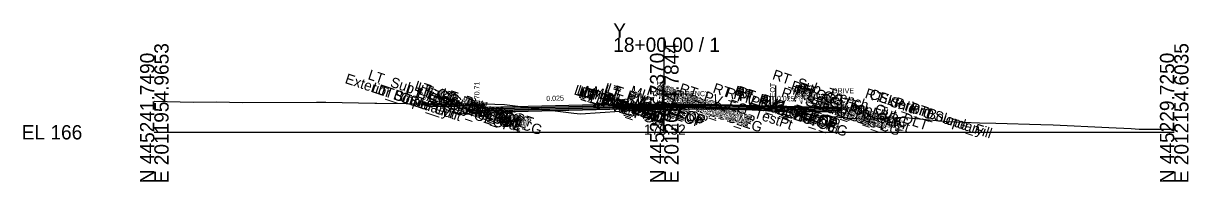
# Model space of a CAD drawing. Extents: x -26 to 3203, y -10 to 9532.
# Drawn here: x 974.3 to 1202.8, y 1990.3 to 2021.4 of the extents above; entities that cross this region are included whole.
import ezdxf

# ---------------------------------------------------------------- set-up
doc = ezdxf.new("R2010")
doc.units = 0
for name, color, linetype in [('Default', 7, 'Continuous'), ('Exist Cross Section Cell', 7, 'Continuous'), ('Exist XS Center Line Elevation Label', 7, 'Continuous'), ('Exist XS Ground Line', 7, 'Continuous'), ('Prop CMT Conc Surface', 7, 'Continuous'), ('Prop CMT Concrete Structures', 7, 'Continuous'), ('Prop CMT Pvmt Course 1', 7, 'Continuous'), ('Prop CMT Pvmt Course 1 CG', 7, 'Continuous'), ('Prop CMT Pvmt Course 1 Wedge', 7, 'Continuous'), ('Prop CMT Pvmt Course 2', 7, 'Continuous'), ('Prop CMT Pvmt Course 2 Wedge', 7, 'Continuous'), ('Prop CMT Pvmt Course 3', 7, 'Continuous'), ('Prop CMT Pvmt Course 3 Wedge', 7, 'Continuous'), ('Prop CMT Pvmt Surface', 7, 'Continuous'), ('Prop CMT Pvmt Wedge Surface 1', 7, 'Continuous'), ('Prop CMT Pvmt Wedge Surface 2', 7, 'Continuous'), ('Prop CMT Pvmt Wedge Surface 3', 7, 'Continuous'), ('Prop CMT Shear Line', 7, 'Continuous'), ('Prop CMT Shear Line Text', 7, 'Continuous'), ('Prop CMT Slope Grass', 7, 'Continuous'), ('Prop CMT Subgrade Earthwork', 7, 'Continuous'), ('Prop XS Hydro Elevations', 7, 'Continuous'), ('Prop XS Label Text', 7, 'Continuous'), ('Prop XS SE Text', 7, 'Continuous'), ('Prop XS Side Slope Text', 7, 'Continuous'), ('Scratch_Level_0', 7, 'Continuous')]:
    doc.layers.add(name, color=color, linetype=linetype)

msp = doc.modelspace()

# ---------------------------------------------------------------- linework, layer by layer
at = {"layer": 'Exist Cross Section Cell'}
for p, q in [((1100, 2000), (1100, 2018.57)), ((1000, 2000), (1100, 2000)), ((1100, 2000), (1200, 2000))]:
    msp.add_line(p, q, dxfattribs=at)
at = {"layer": 'Exist XS Ground Line'}
msp.add_lwpolyline([(1000, 2006.07), (1007.59, 2005.91), (1012.27, 2005.97), (1017.2, 2005.82), (1031.82, 2005.89), (1033.6, 2005.93), (1043.25, 2005.69), (1043.62, 2005.68), (1049.38, 2005.64), (1053.64, 2005.61), (1064.89, 2005.57), (1068.67, 2005.48), (1082.26, 2003.78), (1083.6, 2003.61), (1091.28, 2004.13), (1098.5, 2004.49), (1099.36, 2004.51), (1099.69, 2004.52), (1100, 2004.52), (1101.01, 2004.53), (1102.25, 2004.54), (1102.76, 2004.55), (1104.76, 2004.59), (1105.12, 2004.59), (1107.26, 2004.61), (1109.84, 2004.62), (1110.97, 2004.63), (1112.3, 2004.6), (1114.96, 2004.48), (1117.24, 2004.39), (1117.65, 2004.37), (1119.76, 2004.25), (1120.44, 2004.22), (1121.84, 2004.15), (1122.49, 2004.11), (1122.96, 2004.07), (1124.04, 2004), (1130.14, 2003.3), (1139.23, 2002.57), (1146.62, 2002.97), (1155.38, 2002.09), (1161.79, 2001.83), (1165.05, 2001.79), (1173.87, 2001.53), (1176.25, 2001.44), (1187.16, 2000.92), (1191.57, 2000.71), (1193.13, 2000.63), (1200, 2000.6)], dxfattribs=at)
at = {"layer": 'Prop CMT Conc Surface'}
for points in [[(1058.75, 2005.3), (1053.75, 2005.4)], [(1063.25, 2004.71), (1063.25, 2005.21), (1062.75, 2005.21)], [(1065.25, 2004.84), (1063.25, 2004.71)]]:
    msp.add_lwpolyline(points, dxfattribs=at)
at = {"layer": 'Prop CMT Concrete Structures'}
for p, q in [((1092, 2005.51), (1092, 2005.88)), ((1108, 2005.51), (1108, 2005.88))]:
    msp.add_line(p, q, dxfattribs=at)
for points in [[(1053.75, 2005.07), (1053.75, 2005.4)], [(1053.75, 2005.4), (1058.75, 2005.3)], [(1058.75, 2004.97), (1053.75, 2005.07)], [(1058.75, 2005.3), (1058.75, 2004.97)], [(1065.25, 2004.84), (1063.25, 2004.71), (1063.25, 2005.21), (1062.75, 2005.21)], [(1062.75, 2005.21), (1062.75, 2004.2), (1065.25, 2004.26)], [(1065.25, 2004.26), (1065.25, 2004.84)], [(1092, 2005.51), (1108, 2005.51)]]:
    msp.add_lwpolyline(points, dxfattribs=at)
at = {"layer": 'Prop CMT Pvmt Course 1'}
for points in [[(1092, 2005.51), (1065.25, 2004.84)], [(1065.25, 2004.59), (1092, 2005.26)], [(1065.25, 2004.84), (1065.25, 2004.59)], [(1092, 2005.51), (1108, 2005.51)], [(1092, 2005.26), (1092, 2005.51)], [(1092, 2005.26), (1092, 2005.51)], [(1092, 2005.39), (1092, 2005.26), (1092, 2005.26)], [(1108, 2005.26), (1092, 2005.26)], [(1108, 2005.51), (1108, 2005.26)], [(1108, 2005.51), (1134.75, 2004.84)], [(1108, 2005.26), (1108, 2005.51)], [(1121.84, 2005.04), (1108, 2005.39)], [(1108, 2005.39), (1108, 2005.26), (1108, 2005.26)], [(1121.84, 2004.92), (1121.84, 2005.04)], [(1134.75, 2004.59), (1121.84, 2004.92)]]:
    msp.add_lwpolyline(points, dxfattribs=at)
at = {"layer": 'Prop CMT Pvmt Course 1 CG'}
for points in [[(1065.25, 2004.26), (1062.25, 2004.19), (1061.91, 2003.84)], [(1065.25, 2003.93), (1065.25, 2004.26)], [(1061.91, 2003.84), (1065.25, 2003.93)]]:
    msp.add_lwpolyline(points, dxfattribs=at)
at = {"layer": 'Prop CMT Pvmt Course 1 Wedge'}
for points in [[(1108, 2005.26), (1108, 2005.39)], [(1108, 2005.39), (1109.67, 2005.35), (1109.76, 2005.34), (1109.84, 2005.34), (1110.97, 2005.31), (1112.2, 2005.28), (1112.25, 2005.28), (1112.3, 2005.28), (1114.74, 2005.22), (1114.96, 2005.21), (1117.24, 2005.16), (1117.65, 2005.15), (1119.76, 2005.09), (1120.44, 2005.08), (1121.84, 2005.04)], [(1121.84, 2004.92), (1120.44, 2004.95), (1119.76, 2004.97), (1117.65, 2005.02), (1117.24, 2005.03), (1114.96, 2005.09), (1114.74, 2005.09), (1112.3, 2005.16), (1112.25, 2005.16), (1112.2, 2005.16), (1110.97, 2005.19), (1109.84, 2005.22), (1109.76, 2005.22), (1109.67, 2005.22), (1108, 2005.26)], [(1121.84, 2005.04), (1121.84, 2004.92), (1121.84, 2004.92)]]:
    msp.add_lwpolyline(points, dxfattribs=at)
at = {"layer": 'Prop CMT Pvmt Course 2'}
for points in [[(1092, 2005.26), (1065.25, 2004.59)], [(1065.25, 2004.26), (1092, 2004.93)], [(1065.25, 2004.59), (1065.25, 2004.26)], [(1092, 2005.26), (1108, 2005.26)], [(1092, 2004.93), (1092, 2005.26)], [(1108, 2004.93), (1092, 2004.93)], [(1108, 2005.26), (1108, 2004.93)], [(1121.84, 2004.58), (1121.84, 2004.92)], [(1121.84, 2004.92), (1134.75, 2004.59)], [(1134.75, 2004.26), (1121.84, 2004.58)]]:
    msp.add_lwpolyline(points, dxfattribs=at)
at = {"layer": 'Prop CMT Pvmt Course 2 Wedge'}
for points in [[(1108, 2004.93), (1108, 2005.26)], [(1108, 2005.26), (1109.67, 2005.22), (1109.76, 2005.22), (1109.84, 2005.22), (1110.97, 2005.19), (1112.2, 2005.16), (1112.25, 2005.16), (1112.3, 2005.16), (1114.74, 2005.09), (1114.96, 2005.09), (1117.24, 2005.03), (1117.65, 2005.02), (1119.76, 2004.97), (1120.44, 2004.95), (1121.84, 2004.92)], [(1121.84, 2004.58), (1120.44, 2004.62), (1119.76, 2004.64), (1117.65, 2004.69), (1117.24, 2004.7), (1114.96, 2004.76), (1114.74, 2004.76), (1112.3, 2004.82), (1112.25, 2004.82), (1112.2, 2004.82), (1110.97, 2004.86), (1109.84, 2004.88), (1109.76, 2004.89), (1109.67, 2004.89), (1108, 2004.93)], [(1121.84, 2004.92), (1121.84, 2004.58), (1121.84, 2004.58)]]:
    msp.add_lwpolyline(points, dxfattribs=at)
at = {"layer": 'Prop CMT Pvmt Course 3'}
for points in [[(1092, 2004.93), (1065.25, 2004.26)], [(1065.25, 2003.93), (1092, 2004.6)], [(1065.25, 2004.26), (1065.25, 2003.93)], [(1092, 2004.93), (1108, 2004.93)], [(1092, 2004.6), (1092, 2004.93)], [(1099.69, 2004.6), (1092, 2004.6)], [(1121.84, 2004.58), (1134.75, 2004.26)], [(1121.84, 2004.25), (1121.84, 2004.58)], [(1134.75, 2003.93), (1121.84, 2004.25)]]:
    msp.add_lwpolyline(points, dxfattribs=at)
at = {"layer": 'Prop CMT Pvmt Course 3 Wedge'}
for points in [[(1108, 2004.93), (1109.67, 2004.89), (1109.76, 2004.89), (1109.84, 2004.88), (1110.97, 2004.86), (1112.2, 2004.82), (1112.25, 2004.82), (1112.3, 2004.82), (1114.74, 2004.76), (1114.96, 2004.76), (1117.24, 2004.7), (1117.65, 2004.69), (1119.76, 2004.64), (1120.44, 2004.62), (1121.84, 2004.58)], [(1124.04, 2004), (1123.94, 2004.01), (1122.96, 2004.07), (1122.49, 2004.11), (1122.26, 2004.13), (1122.07, 2004.14), (1121.84, 2004.15), (1120.44, 2004.22), (1119.76, 2004.25), (1117.65, 2004.37), (1117.24, 2004.39), (1114.96, 2004.48), (1114.74, 2004.49), (1112.3, 2004.6), (1112.25, 2004.6), (1112.2, 2004.6), (1110.97, 2004.63), (1109.84, 2004.62), (1109.76, 2004.62), (1109.67, 2004.62), (1108, 2004.61)], [(1121.84, 2004.58), (1121.84, 2004.15)]]:
    msp.add_lwpolyline(points, dxfattribs=at)
at = {"layer": 'Prop CMT Pvmt Surface'}
for points in [[(1092, 2005.51), (1065.25, 2004.84)], [(1092, 2005.51), (1108, 2005.51)], [(1108, 2005.51), (1134.75, 2004.84)]]:
    msp.add_lwpolyline(points, dxfattribs=at)
at = {"layer": 'Prop CMT Pvmt Wedge Surface 1'}
for points in [[(1108, 2005.51), (1108, 2005.26), (1108, 2005.26), (1108, 2005.39)], [(1108, 2005.39), (1121.84, 2005.04)], [(1121.84, 2005.04), (1121.84, 2004.92)], [(1121.84, 2004.92), (1134.75, 2004.59)]]:
    msp.add_lwpolyline(points, dxfattribs=at)
at = {"layer": 'Prop CMT Pvmt Wedge Surface 2'}
for points in [[(1108, 2005.51), (1108, 2005.26)], [(1108, 2005.26), (1134.75, 2004.59)]]:
    msp.add_lwpolyline(points, dxfattribs=at)
at = {"layer": 'Prop CMT Pvmt Wedge Surface 3'}
for points in [[(1108, 2005.51), (1108, 2004.93)], [(1108, 2004.93), (1134.75, 2004.26)]]:
    msp.add_lwpolyline(points, dxfattribs=at)
at = {"layer": 'Prop CMT Shear Line'}
msp.add_line((1134.75, 2002.84), (1134.75, 2007.42), dxfattribs=at)
at = {"layer": 'Prop CMT Slope Grass'}
msp.add_lwpolyline([(1062.75, 2005.21), (1053.25, 2005.4), (1052.6, 2005.62)], dxfattribs=at)
at = {"layer": 'Prop CMT Subgrade Earthwork'}
msp.add_line((1099.69, 2004.6), (1099.69, 2004.52), dxfattribs=at)
for points in [[(1065.25, 2003.93), (1061.91, 2003.84), (1060.49, 2005.26)], [(1092, 2004.6), (1065.25, 2003.93)], [(1092, 2004.6), (1099.69, 2004.6)], [(1121.84, 2004.25), (1134.75, 2003.93)], [(1121.84, 2004.25), (1121.84, 2004.15)]]:
    msp.add_lwpolyline(points, dxfattribs=at)
at = {"layer": 'Prop XS Label Text'}
for p, q in [((1099.69, 2009.52), (1099.69, 2004.52)), ((1121.84, 2009.15), (1121.84, 2004.15))]:
    msp.add_line(p, q, dxfattribs=at)

# ---------------------------------------------------------------- texts
at = {"layer": 'Default'}
msp.add_text('-', height=0.0001, dxfattribs=at).set_placement((1000, 2000))
at = {"layer": 'Exist Cross Section Cell'}
for s, p in [('Y', (1090, 2018.57)), ('18+00.00 / 1', (1090, 2015.77)), ('EL 166', (974, 1998.6))]:
    msp.add_text(s, height=2.8, dxfattribs=at).set_placement(p)
for s, p in [('E 2011954.9653', (1002.8, 1990)), ('E 2012054.7844', (1102.8, 1990)), ('E 2012154.6035', (1202.8, 1990)), ('N 445241.7490', (1000, 1990)), ('N 445235.7370', (1100, 1990)), ('N 445229.7250', (1200, 1990))]:
    msp.add_text(s, height=2.8, rotation=90, dxfattribs=at).set_placement(p)
at = {"layer": 'Exist XS Center Line Elevation Label'}
msp.add_text('170.52', height=2, dxfattribs=at).set_placement((1096.03, 1999.52))
at = {"layer": 'Prop CMT Shear Line Text'}
for s, p in [('EMERGENCY', (1100.01, 2007.08)), ('ACCESS', (1101.46, 2005.77)), ('DRIVE', (1132.99, 2007.64))]:
    msp.add_text(s, height=1, rotation=360, dxfattribs=at).set_placement(p)
at = {"layer": 'Prop XS Hydro Elevations'}
msp.add_text('170.71', height=1, rotation=90, dxfattribs=at).set_placement((1063.75, 2005.71))
at = {"layer": 'Prop XS Label Text'}
for p in [(1099.59, 2005.55), (1121.74, 2005.18)]:
    msp.add_text('E. EOT', height=1, rotation=90, dxfattribs=at).set_placement(p)
at = {"layer": 'Prop XS SE Text'}
for rotation, p in [(1.4321, (1076.87, 2006.13)), (358.5679, (1122.08, 2006.16))]:
    msp.add_text('0.025', height=1, rotation=rotation, dxfattribs=at).set_placement(p)
at = {"layer": 'Prop XS Side Slope Text'}
msp.add_text('3:1', height=1, rotation=341.5651, dxfattribs=at).set_placement((1052.42, 2006.47))
at = {"layer": 'Scratch_Level_0'}
for s, p in [('Exterior Boundary', (1037.25, 2009.68)), ('LT_Sub_Trench_Out_DLT', (1041.74, 2010.46)), ('RT_Sub_Trench_Out_DLT', (1121.07, 2010.46)), ('LT_Slope_Cut', (1042.47, 2007.94)), ('LT_CSLP_Pnt', (1043.61, 2007.56)), ('LT_CG1_Shelf_Out', (1049.18, 2007.49)), ('LT_CG_Top_Face', (1050.85, 2008.29)), ('LT_CG_Top_BOC', (1051.32, 2007.97)), ('LT_CG_Top_Gut', (1051.77, 2007.49)), ('LT_PV2_IEEOP', (1082.15, 2007.49)), ('LT_PV1_IEEOP', (1082.69, 2007.44)), ('LT_PV2_PGL1', (1083.03, 2007.2)), ('LT_PV2_PGL', (1083.35, 2007.09)), ('LT_PV1_PGL', (1083.89, 2007.16)), ('MI_Face In', (1084, 2007.3)), ('MI_Top In', (1085.66, 2007.24)), ('LT_Sub_OEEOP', (1087.96, 2007.22)), ('LT_PV2_OEEOP', (1088.05, 2007.86)), ('LT_PV3_OEEOP', (1088.05, 2007.53)), ('LT_PV1_OEEOP', (1088.59, 2007.8)), ('MI_Crown', (1093.11, 2007.32)), ('RT_PV_IEEOP_EG', (1096.43, 2007.41)), ('RT_PV2_IEEOP', (1098.11, 2007.51)), ('RT_PV3_IEEOP', (1098.11, 2007.17)), ('MI_Face Out', (1098.44, 2007.81)), ('MI_Top Out', (1098.6, 2007.75)), ('RT_PV1_IEEOP', (1098.65, 2007.45)), ('RT_PV2_PGL1', (1098.99, 2007.21)), ('RT_PV2_PGL', (1099.3, 2007.11)), ('MI_Bot Out', (1099.39, 2007.33)), ('RT_PV1_PGL', (1099.84, 2007.18)), ('RT_PV_EG_TestPt', (1102.77, 2007.8)), ('RT_PV_Sub_Tie_Out', (1109.38, 2007.83)), ('RT_PV_OEEOP_EG', (1111.86, 2007.01)), ('RT_PV2_OEEOP', (1113.53, 2007.31)), ('RT_PV3_OEEOP', (1113.53, 2006.98)), ('RT_PV1_OEEOP', (1114.07, 2007.26)), ('RT_Sub_OEOT_CG', (1122.77, 2006.98)), ('RT_CG_Top_Face', (1124.66, 2008.3)), ('RT_CG1_Shelf_Out', (1124.99, 2007.5)), ('RT_CG_Top_Gut', (1125.59, 2007.49)), ('RT_CG_Top_BOC', (1126.13, 2007.98)), ('LT_CG_Bot_BOC', (1051.35, 2006.94)), ('LT_Sub_OEOP', (1052.21, 2006.02)), ('LT_Sub_OEOT_CG', (1052.95, 2006.97)), ('LT_CG_Bot_IE', (1055.36, 2006.5)), ('LT_Sub_OEOT', (1055.52, 2006.12)), ('LT_PV2_OEOT', (1055.61, 2006.75)), ('LT_PV3_OEOT', (1055.61, 2006.42)), ('LT_PV1_OEOT', (1056.15, 2006.82)), ('LT_PV3_PGL1', (1083.03, 2006.86)), ('LT_PV4_PGL', (1083.35, 2006.43)), ('RT_PV3_PGL1', (1098.99, 2006.88)), ('RT_PV3_PGL', (1099.3, 2006.77)), ('RT_PV4_PGL', (1099.3, 2006.44)), ('RT_Sub_OEEOP', (1113.44, 2006.67)), ('RT_CG_Bot_IE', (1125.18, 2006.51)), ('RT_Sub_OEOT', (1125.34, 2006.12)), ('RT_PV2_OEOT', (1125.43, 2006.76)), ('RT_PV3_OEOT', (1125.43, 2006.43)), ('RT_PV1_OEOT', (1125.96, 2006.83)), ('RT_CG_Bot_BOC', (1126.16, 2006.95)), ('RT_Sub_OEOP', (1128.71, 2006.03)), ('RT_Shld_O', (1139.21, 2006.8)), ('CSLP_Pnt', (1140.03, 2006.7)), ('Exterior Boundary', (1141.92, 2006.07)), ('RT_Slope_Fill', (1147.93, 2004.07))]:
    msp.add_text(s, height=2, rotation=341.5651, dxfattribs=at).set_placement(p)

doc.saveas('drawing.dxf')
